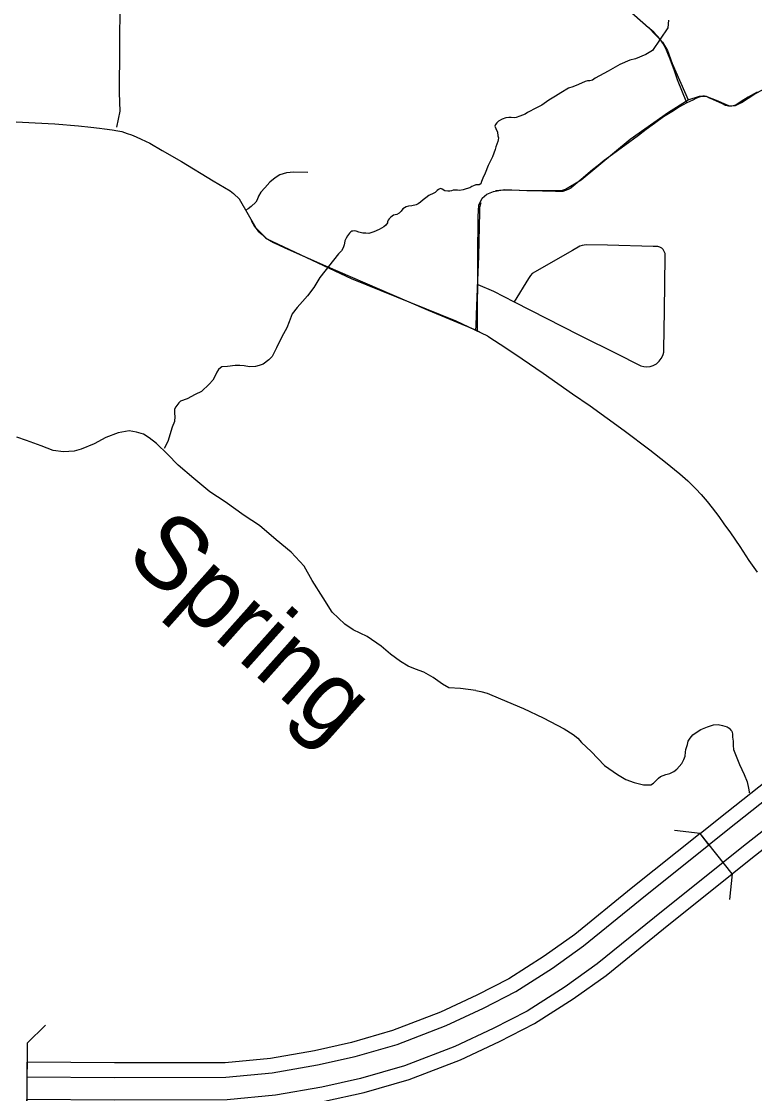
# Model space of a CAD drawing. Extents: x 670147 to 673275, y 705573 to 707613.
# Drawn here: x 671348.9 to 671434.3, y 706128.4 to 706253.2 of the extents above; entities that cross this region are included whole.
import ezdxf

# ---------------------------------------------------------------- set-up
doc = ezdxf.new("R2010")
doc.units = 0
for name, color, linetype in [('10', 7, 'Continuous'), ('31', 7, 'Continuous'), ('32', 7, 'Continuous'), ('33', 7, 'Continuous'), ('34', 7, 'Continuous'), ('35', 7, 'Continuous'), ('39', 7, 'Continuous'), ('6', 7, 'Continuous')]:
    doc.layers.add(name, color=color, linetype=linetype)

msp = doc.modelspace()

# ---------------------------------------------------------------- linework, layer by layer
at = {"layer": '10'}
msp.add_line((671428.96, 706157.34), (671427.91, 706158.65), dxfattribs=at)
for points in [[(671427.91, 706158.65), (671430.09, 706160.4), (671435.67, 706164.81)], [(671436.71, 706163.49), (671431.13, 706159.08), (671428.96, 706157.34)], [(671438.35, 706161.41), (671432.77, 706157.01), (671430.6, 706155.28)], [(671431.65, 706153.97), (671433.82, 706155.7), (671439.39, 706160.1)], [(671428.95, 706157.34), (671427.91, 706158.65), (671419.88, 706152.24), (671413.33, 706146.9), (671409.78, 706144.37), (671405.64, 706141.73), (671401.94, 706139.83), (671397.7, 706137.85), (671392.13, 706135.71), (671387.34, 706134.33), (671383.05, 706133.37), (671377.91, 706132.46), (671372.66, 706131.96), (671359.78, 706131.95), (671349.59, 706132.02), (671349.57, 706130.34)], [(671349.57, 706130.34), (671359.77, 706130.27), (671372.74, 706130.28), (671378.13, 706130.8), (671383.38, 706131.72), (671387.76, 706132.7), (671392.66, 706134.11), (671398.36, 706136.3), (671402.69, 706138.32), (671406.47, 706140.27), (671410.72, 706142.98), (671414.35, 706145.57), (671420.94, 706150.93), (671428.95, 706157.34)], [(671431.65, 706153.97), (671430.6, 706155.28), (671422.59, 706148.88), (671415.95, 706143.47), (671412.2, 706140.79), (671407.79, 706137.98), (671403.85, 706135.95), (671399.39, 706133.87), (671393.5, 706131.61), (671388.41, 706130.14), (671383.89, 706129.13), (671378.49, 706128.18), (671372.87, 706127.64), (671359.76, 706127.63), (671349.56, 706127.7), (671349.51, 706126.02)], [(671349.51, 706126.02), (671359.76, 706125.95), (671372.95, 706125.96), (671378.71, 706126.51), (671384.22, 706127.48), (671388.83, 706128.51), (671394.04, 706130.01), (671400.05, 706132.32), (671404.59, 706134.44), (671408.63, 706136.52), (671413.14, 706139.39), (671416.97, 706142.13), (671423.65, 706147.57), (671431.65, 706153.97)]]:
    msp.add_lwpolyline(points, dxfattribs=at)
at = {"layer": '31'}
for points in [[(671382.26, 706235.59), (671380.62, 706235.62), (671379.8, 706235.54), (671379, 706235.33), (671378.48, 706234.97), (671377.83, 706234.45), (671377.25, 706233.82), (671376.8, 706233.31), (671376.52, 706232.84), (671376.39, 706232.42), (671376.21, 706232.15), (671375.69, 706231.64), (671375.34, 706231.38), (671375.06, 706231.22)], [(671375.67, 706230.02), (671376.08, 706229.31), (671376.5, 706228.77), (671376.94, 706228.36), (671377.35, 706228), (671377.81, 706227.71), (671378.28, 706227.44), (671379.01, 706227.1), (671379.93, 706226.66), (671384.31, 706224.74), (671392.03, 706221.38), (671396.27, 706219.56), (671401.77, 706217.28), (671402.24, 706217.03)], [(671402.12, 706225.86), (671401.99, 706222.09), (671401.86, 706219.06), (671401.81, 706217.71), (671401.77, 706217.28)]]:
    msp.add_lwpolyline(points, dxfattribs=at)
at = {"layer": '32'}
for points in [[(671426.38, 706243.71), (671425.29, 706246.39), (671424.92, 706247.42), (671424.45, 706248.78), (671424.16, 706249.44), (671423.92, 706250.01), (671423.57, 706250.64), (671423.25, 706251.12), (671422.87, 706251.53), (671422.54, 706251.91), (671421.81, 706252.54), (671420.96, 706253.29)], [(671434.55, 706244.95), (671433.51, 706244.37), (671432.68, 706243.85), (671432.19, 706243.51), (671431.91, 706243.39), (671431.62, 706243.3), (671431.22, 706243.31), (671430.87, 706243.41), (671430.54, 706243.57), (671429.41, 706244.09), (671428.94, 706244.3), (671428.65, 706244.43), (671428.44, 706244.47), (671428.22, 706244.46), (671427.93, 706244.39), (671427.48, 706244.23), (671427.08, 706244.02), (671426.38, 706243.71)], [(671426.38, 706243.71), (671425.51, 706243.23), (671424.62, 706242.65), (671423.67, 706242.07), (671422.6, 706241.31), (671421.62, 706240.58), (671420.73, 706239.91), (671419.14, 706238.72), (671418.3, 706238.11), (671417.29, 706237.38), (671416.75, 706236.99), (671416.5, 706236.79), (671416.04, 706236.42), (671415.41, 706235.89), (671414.88, 706235.47), (671414.09, 706234.76), (671413.16, 706234.02), (671412.88, 706233.78), (671412.58, 706233.61), (671412.26, 706233.49), (671411.93, 706233.4), (671411.54, 706233.37), (671411.1, 706233.37), (671409.56, 706233.42), (671406.85, 706233.51), (671405.08, 706233.52), (671404.57, 706233.51), (671404.09, 706233.46)], [(671402.39, 706232.07), (671402.31, 706231.83), (671402.26, 706231.5), (671402.23, 706231.01), (671402.12, 706225.86)]]:
    msp.add_lwpolyline(points, dxfattribs=at)
at = {"layer": '33'}
for points in [[(671348.34, 706241.5), (671350.55, 706241.36), (671352.83, 706241.26), (671355.57, 706241.01), (671357.03, 706240.88), (671358.03, 706240.75), (671358.6, 706240.69), (671359.51, 706240.56), (671360.17, 706240.45), (671360.64, 706240.35), (671361.24, 706240.15), (671361.75, 706239.98), (671362.28, 706239.76), (671362.88, 706239.49), (671363.87, 706239), (671365.3, 706238.16), (671367.55, 706236.86), (671371.25, 706234.62), (671373.22, 706233.45), (671373.6, 706233.16), (671374.31, 706232.48)], [(671403.21, 706216.56), (671399.52, 706218.28), (671387.34, 706223.22), (671377.53, 706227.85), (671376.25, 706229.13), (671374.31, 706232.48)], [(671402.04, 706222.55), (671403.87, 706221.77), (671406.27, 706220.55), (671413.8, 706216.69), (671418.4, 706214.42), (671420.64, 706213.29), (671421.03, 706213.1), (671421.35, 706213.01), (671421.73, 706212.98), (671422.1, 706213.01), (671422.46, 706213.11), (671422.84, 706213.33), (671423.15, 706213.63), (671423.39, 706213.93), (671423.53, 706214.2), (671423.61, 706214.42), (671423.69, 706214.69), (671423.7, 706215), (671423.77, 706219.55), (671423.83, 706225.81), (671423.83, 706226.16), (671423.74, 706226.4), (671423.61, 706226.63), (671423.45, 706226.78), (671423.23, 706226.91), (671423, 706226.97), (671422.47, 706226.98), (671417.14, 706227.14)], [(671417.14, 706227.14), (671414.67, 706227.16), (671414.19, 706227.1), (671413.91, 706227), (671413.06, 706226.52), (671408.39, 706223.84), (671408.17, 706223.62), (671407.93, 706223.27), (671406.27, 706220.55)], [(671402.02, 706217.12), (671402.05, 706225.71)], [(671403.21, 706216.56), (671405.42, 706215.09), (671407.19, 706213.91), (671409.65, 706212.25), (671413.08, 706209.85), (671415.12, 706208.42), (671419.06, 706205.55), (671422.06, 706203.33), (671423.87, 706201.87), (671425.56, 706200.51), (671426.48, 706199.71), (671427.11, 706199.09), (671427.41, 706198.79), (671428.02, 706198.11), (671428.73, 706197.3), (671429.32, 706196.56), (671430.09, 706195.56), (671430.67, 706194.68), (671431.44, 706193.66), (671432.53, 706192.08), (671433.6, 706190.42), (671434.55, 706189.07)]]:
    msp.add_lwpolyline(points, dxfattribs=at)
at = {"layer": '34'}
for points in [[(671402.79, 706287.33), (671405.07, 706286.88), (671407.1, 706286.68), (671414.28, 706286.83), (671415.23, 706286.7), (671415.55, 706286.41), (671415.79, 706285.96), (671415.77, 706285.22), (671415.61, 706274.54), (671415.7, 706266.9), (671415.75, 706263.94), (671415.71, 706261.44), (671415.84, 706260.19), (671416.43, 706257.74), (671417.59, 706256.39), (671418.67, 706255.35), (671421.9, 706252.46), (671423.55, 706250.76), (671424.14, 706249.81), (671424.66, 706248.29), (671426.54, 706244.07)], [(671402.05, 706225.71), (671402.07, 706230.49), (671402.16, 706231.79), (671402.55, 706232.61), (671403.09, 706233.08), (671403.88, 706233.37), (671405.17, 706233.62), (671407.74, 706233.51), (671411.79, 706233.51), (671412.24, 706233.65), (671414.07, 706234.75), (671419.79, 706239.48), (671424.24, 706242.61), (671426.54, 706244.07), (671427.86, 706244.48), (671428.58, 706244.47), (671429.79, 706244), (671430.93, 706243.49), (671431.35, 706243.37), (671432.04, 706243.4), (671432.75, 706243.74), (671434.15, 706244.69), (671435.36, 706245.32)]]:
    msp.add_lwpolyline(points, dxfattribs=at)
at = {"layer": '35'}
for points in [[(671424.24, 706253.32), (671424.15, 706252.43), (671422.38, 706249.81)], [(671422.38, 706249.81), (671421.61, 706249.31), (671420.4, 706248.81), (671419.73, 706248.68), (671418.56, 706248.16), (671417.23, 706247.39), (671415.7, 706246.59), (671415.39, 706246.36), (671415.1, 706246.28), (671414.81, 706246.26), (671414.54, 706246.18), (671413.78, 706245.84), (671413.1, 706245.55), (671412.59, 706245.4), (671411.7, 706244.88), (671411.09, 706244.49), (671410.3, 706244.01), (671409.48, 706243.42), (671408.88, 706243.13), (671407.81, 706242.57), (671407.55, 706242.39), (671406.92, 706242.17), (671406.51, 706241.99), (671406.26, 706241.96), (671405.93, 706242), (671405.66, 706242), (671405.29, 706241.96), (671404.88, 706241.8), (671404.47, 706241.58), (671404.25, 706241.39), (671404.1, 706241.18), (671404.04, 706240.98), (671404.15, 706240.72), (671404.32, 706240.28), (671404.39, 706239.85), (671404.45, 706239.61), (671404.42, 706239.39), (671404.38, 706239.21), (671404.15, 706238.58), (671404.08, 706238.27), (671403.75, 706237.4), (671403.27, 706236.41), (671402.89, 706235.51), (671402.64, 706234.94), (671402.49, 706234.54), (671402.41, 706234.28), (671402.19, 706234.15), (671401.98, 706234.15), (671401.8, 706234.14), (671401.55, 706234.05), (671401.35, 706233.95), (671401.1, 706233.81), (671400.7, 706233.68), (671400.33, 706233.57), (671399.91, 706233.51), (671399.67, 706233.53), (671399.41, 706233.54), (671399.17, 706233.53), (671398.98, 706233.47), (671398.78, 706233.41), (671398.55, 706233.43), (671398.22, 706233.47), (671397.88, 706233.64), (671397.73, 706233.72), (671397.62, 706233.7), (671397.47, 706233.63), (671397.32, 706233.51), (671397.24, 706233.41), (671397.1, 706233.26), (671396.94, 706233.19), (671396.35, 706232.9), (671395.99, 706232.65), (671395.68, 706232.42), (671395.36, 706232.14), (671395.09, 706231.95), (671394.87, 706231.82), (671394.37, 706231.72)], [(671394.37, 706231.72), (671393.99, 706231.66), (671393.72, 706231.59), (671393.51, 706231.48), (671393.32, 706231.36), (671393.11, 706231.1), (671392.88, 706230.86), (671392.61, 706230.7), (671392.24, 706230.61), (671391.91, 706230.4), (671391.72, 706230.2), (671391.61, 706230.03), (671391.55, 706229.86), (671391.52, 706229.72), (671391.35, 706229.48), (671391.12, 706229.28), (671390.57, 706228.95), (671389.96, 706228.69), (671389.35, 706228.51), (671389.03, 706228.52), (671388.65, 706228.55), (671388.21, 706228.65), (671387.91, 706228.77), (671387.67, 706228.79), (671387.52, 706228.78), (671387.38, 706228.76), (671387.26, 706228.69), (671387.11, 706228.55), (671386.87, 706228.24), (671386.74, 706227.95), (671386.58, 706227.64), (671386.52, 706227.37), (671386.5, 706227.18), (671386.37, 706226.83), (671386.18, 706226.49), (671385.96, 706226.26), (671385.85, 706226.13), (671383.66, 706223.39)], [(671383.66, 706223.39), (671382.96, 706222.22), (671382.23, 706221.25), (671381.63, 706220.58), (671381.03, 706219.88), (671380.45, 706219.15), (671380.08, 706218.2), (671379.81, 706217.52), (671379.25, 706216.48), (671378.63, 706215.2), (671378.13, 706214.16), (671377.73, 706213.77), (671377.07, 706213.27), (671376.59, 706213.12), (671376.18, 706213.02), (671375.49, 706212.98), (671374.87, 706213.1), (671374.35, 706213.14), (671373.82, 706213.12), (671372.9, 706213.02), (671372.26, 706212.98), (671372.09, 706212.87), (671371.89, 706212.67), (671371.69, 706212.34), (671371.44, 706211.85), (671371.23, 706211.41), (671370.78, 706210.94), (671369.89, 706210.09), (671369.16, 706209.75), (671368.21, 706209.26), (671367.46, 706208.97), (671367.25, 706208.78), (671366.9, 706208.32), (671366.76, 706208.03), (671366.76, 706207.54), (671366.8, 706207.2), (671366.74, 706206.6), (671366.47, 706205.96), (671365.97, 706204.3), (671365.55, 706203.47)], [(671401.8, 706175.28), (671400.02, 706175.52), (671398.69, 706175.61), (671397.93, 706176.05), (671396.87, 706176.81), (671395.76, 706177.43), (671394.78, 706177.78), (671393.94, 706178.14), (671393.05, 706178.67), (671391.9, 706179.51), (671390.79, 706180.45), (671389.19, 706181.6), (671387.55, 706182.35), (671386.58, 706183.02), (671385.11, 706184.4), (671384.05, 706186.08), (671382.76, 706188.12), (671381.83, 706189.76), (671380.32, 706191.41), (671378.59, 706192.83), (671376.64, 706194.51), (671374.87, 706195.67), (671372.65, 706197.26), (671370.87, 706198.42), (671369.01, 706199.97), (671367.19, 706201.52), (671365.95, 706202.81), (671364.66, 706204.05), (671363.82, 706204.72), (671363.13, 706205.15), (671362.33, 706205.37), (671361.49, 706205.51), (671360.2, 706205.29), (671358.78, 706204.75), (671357.41, 706204), (671355.9, 706203.38), (671355.06, 706203.16), (671353.82, 706203.07), (671352.62, 706203.24), (671351.24, 706203.78), (671349.51, 706204.4), (671348.4, 706204.8)], [(671401.8, 706175.28), (671402.38, 706175.2), (671403.15, 706174.97), (671404.68, 706174.31), (671407.36, 706173.19), (671409.66, 706172.13), (671412.1, 706170.83), (671413.16, 706170.16), (671413.68, 706169.75), (671414.12, 706169.25), (671415.22, 706168.2), (671416.78, 706166.55), (671418.29, 706165.51), (671419.29, 706164.95), (671420.24, 706164.58), (671421.33, 706164.33), (671421.95, 706164.31), (671422.2, 706164.31), (671422.51, 706164.51), (671422.72, 706164.76), (671423.09, 706165.1), (671423.32, 706165.28), (671423.61, 706165.39), (671423.92, 706165.51), (671424.39, 706165.63), (671424.87, 706165.86), (671425.2, 706166.13), (671425.78, 706166.8), (671426.03, 706167.25), (671426.16, 706167.65), (671426.22, 706168.12), (671426.26, 706168.45), (671426.43, 706169.03), (671426.53, 706169.41), (671426.74, 706169.76), (671427.05, 706170.13), (671427.44, 706170.4), (671428, 706170.75), (671428.79, 706171.06), (671429.47, 706171.29), (671430.03, 706171.33), (671430.51, 706171.23), (671431.07, 706171.08), (671431.28, 706170.92), (671431.51, 706170.67), (671431.59, 706170.55), (671431.69, 706170.26), (671431.69, 706169.86), (671431.75, 706169.41), (671431.76, 706168.91), (671431.8, 706168.45), (671432.13, 706167.65), (671432.48, 706166.69), (671433.03, 706165.54), (671433.4, 706164.65), (671433.53, 706163.93), (671433.61, 706163.51), (671433.64, 706163.37)]]:
    msp.add_lwpolyline(points, dxfattribs=at)
at = {"layer": '39'}
for p, q in [((671427.91, 706158.65), (671424.92, 706158.99)), ((671431.65, 706153.97), (671427.91, 706158.65)), ((671431.65, 706153.97), (671431.32, 706150.98)), ((671349.6, 706134.26), (671349.5, 706123.7))]:
    msp.add_line(p, q, dxfattribs=at)
msp.add_lwpolyline([(671351.74, 706136.36), (671349.6, 706134.26)], dxfattribs=at)
at = {"layer": '6'}
msp.add_lwpolyline([(671415.68, 706263.92), (671409.97, 706262.38), (671402.24, 706260.28), (671402.24, 706260.41), (671376.28, 706260.92), (671375.97, 706260.91), (671367.53, 706260.74), (671366.38, 706260.71), (671364.71, 706260.73), (671363.04, 706260.74), (671361.37, 706260.76), (671360.43, 706260.81), (671360.31, 706244.87), (671360.39, 706242.75), (671359.99, 706240.86)], dxfattribs=at)

# ---------------------------------------------------------------- texts
at = {"layer": '35'}
msp.add_text('Spring', height=8.448, rotation=318.2395, dxfattribs=at).set_placement((671360.83, 706190.7))

doc.saveas('drawing.dxf')
